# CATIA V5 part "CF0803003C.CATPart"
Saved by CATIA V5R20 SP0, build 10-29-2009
Part number: FC-3-A-Tooling
Bounding box of the stored display mesh (mm): x -45.905 to 47.7, y -45.905 to 54.06, z 0 to 31
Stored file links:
  C:\Users\Raffaele\Desktop\3D X SITO CF\A-TOOLING\FC-3-A-Tooling.CATPart
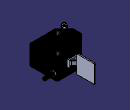
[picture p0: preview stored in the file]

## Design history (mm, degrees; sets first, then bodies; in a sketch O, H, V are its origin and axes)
Set1
  DatumSurface1 to DatumSurface836
Body1 (main body)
